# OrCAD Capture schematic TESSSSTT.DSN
size A
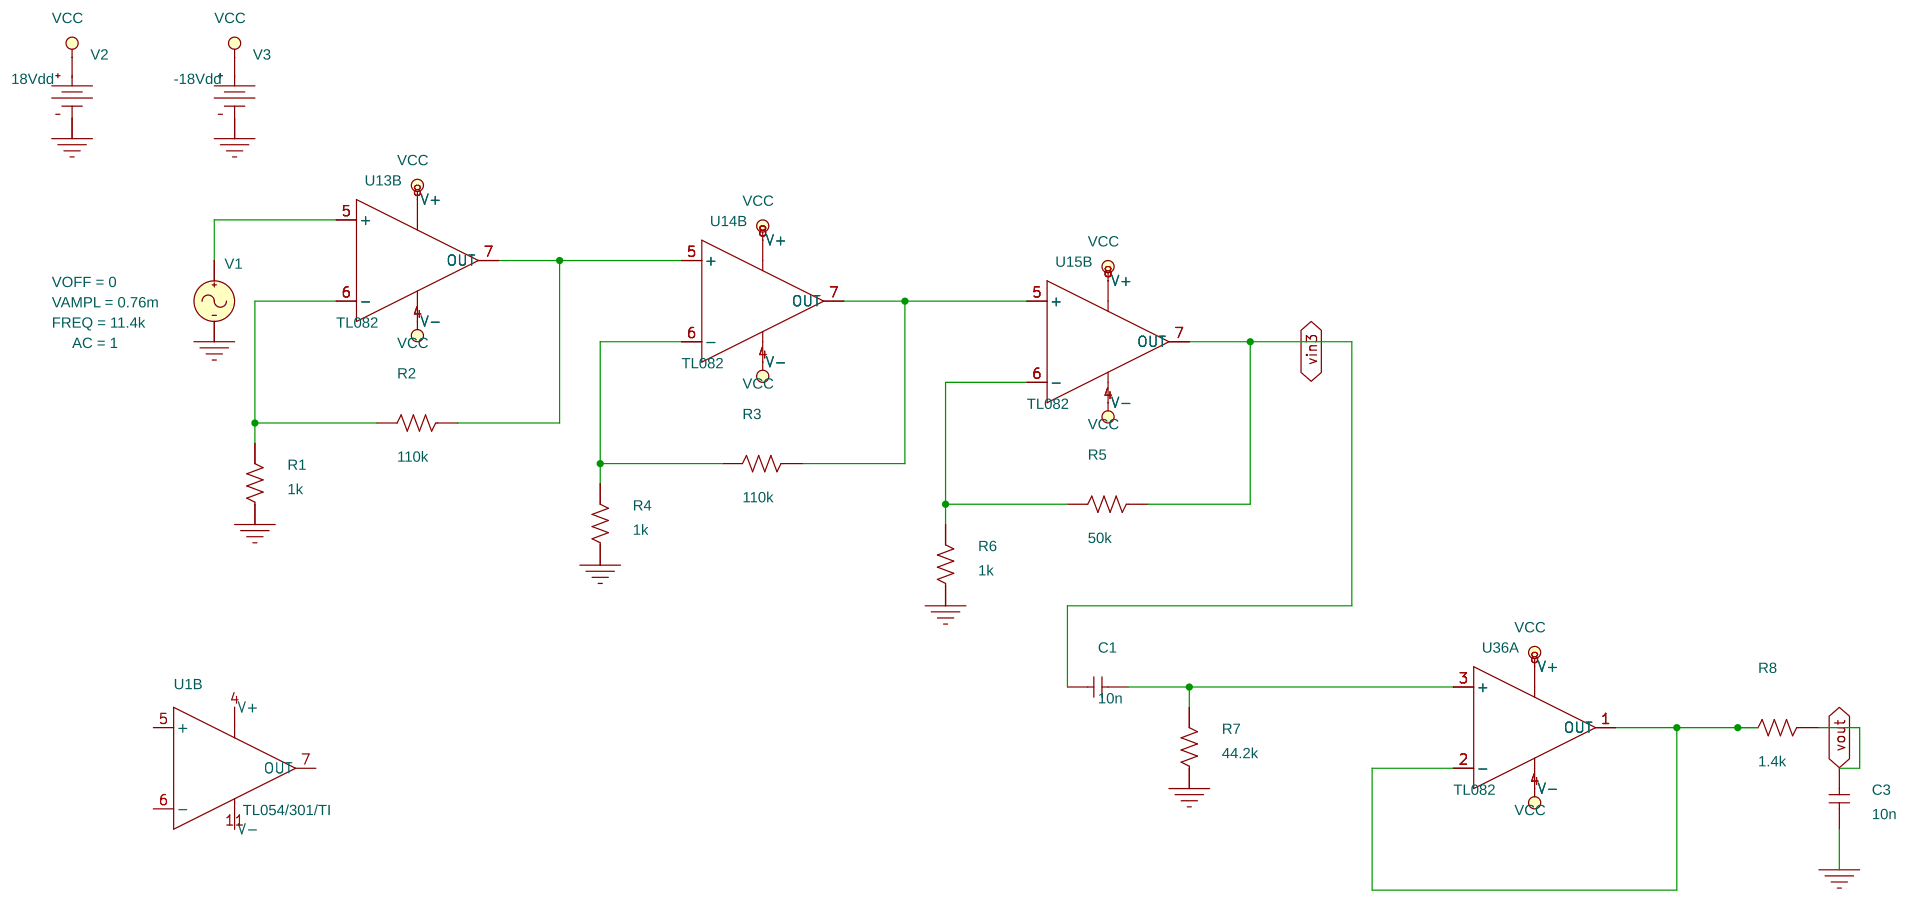
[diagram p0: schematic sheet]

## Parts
C1  10n  [RAD/CK05]
C3  10n  [RAD/CK05]
R1  1k  [AX/RC05]
R2  110k  [AX/RC05]
R3  110k  [AX/RC05]
R4  1k  [AX/RC05]
R5  50k  [AX/RC05]
R6  1k  [AX/RC05]
R7  44.2k  [AX/RC05]
R8  1.4k  [AX/RC05]
U1  TL054/301/TI  [DIP.100/14/W.300/L.800]  (section B)
U13  TL082  [DIP.100/8/W.300/L.450]  (section B)
U14  TL082  [DIP.100/8/W.300/L.450]  (section B)
U15  TL082  [DIP.100/8/W.300/L.450]  (section B)
U36  TL082  [DIP.100/8/W.300/L.450]  (section A)
V1  VSIN
V2  VDC
V3  VDC

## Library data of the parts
C1 C3 = C
R1-R8 = R
U1 = TL054_301_TI
U13-U15 U36 = TL082
V1 = VSIN: AC: 1; FREQ: 11.4k; VAMPL: 0.76m; VOFF: 0
V2 = VDC: DC: 18Vdd
V3 = VDC: DC: -18Vdd

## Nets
0: C3.1 R1.1 R4.1 R6.1 R7.1 V1.2(-) V2.1(-) V3.1(-)
+18: U13.8(V+) U14.8(V+) U15.8(V+) U36.8(V+) V2.0(+)
-18: U13.4(V-) U14.4(V-) U15.4(V-) U36.4(V-) V3.0(+)
V+: U1.4(V+)
V-: U1.11(V-)
N12650: R2.1 U13.7(OUT) U14.5(+)
N12702: R1.2 R2.2 U13.6(-)
N15394: U13.5(+) V1.1(+)
N16134: R3.1 U14.7(OUT) U15.5(+)
N16144: R3.2 R4.2 U14.6(-)
N16429: C1.1 R5.1 U15.7(OUT)
N16439: R5.2 R6.2 U15.6(-)
N22338: C1.2 R7.2 U36.3(+)
N22396: R8.2 U36.1(OUT) U36.2(-)
N22412: C3.2 R8.1

Not connected (* = marked no-connect by the designer): U1 5(+) 6(-) 7(OUT)
